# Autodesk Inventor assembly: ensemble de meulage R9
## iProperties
Shininess: 64.0
Length Units: 11269
Angle Units: 11279
Time Units: 11290
Mass Units: 11283
Length Display Precision: 3
Angle Display Precision: 2
Compacted: True
Created: 2004-12
Part Number: ensemble de meulage R9
Document SubType Name: Assembly
Designer: LEGERET Philippe
Density: 0.0
Volumn: 0.0
Area: 0.0
PropertySet Name: Model Information
Control State: 0
Master: False
Checked Out: False
Author: LEGERET Philippe
